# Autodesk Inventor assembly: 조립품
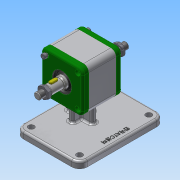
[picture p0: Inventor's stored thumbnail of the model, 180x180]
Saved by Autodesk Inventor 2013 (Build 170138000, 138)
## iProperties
Created: 2020-11
Part Number: 조립품
Document SubType Name: Assembly
Designer: Administrator
Author: Administrator
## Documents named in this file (10)
- C:\Users\Administrator\Desktop\701106V1009\조립품.iam
- C:\Users\Administrator\Desktop\701106V1009\본체.ipt
- C:\Users\Administrator\Desktop\701106V1009\V-벨트풀리.ipt
- C:\Users\Administrator\Desktop\701106V1009\너트 M10x1.ipt
- C:\Users\Administrator\Desktop\701106V1009\베어링 6004.ipt
- C:\Users\Administrator\Desktop\701106V1009\볼트 M4.ipt
- C:\Users\Administrator\Desktop\701106V1009\오일 실 17 30 5.ipt
- C:\Users\Administrator\Desktop\701106V1009\축.ipt
- C:\Users\Administrator\Desktop\701106V1009\커버.ipt
- C:\Users\Administrator\Desktop\701106V1009\키 5 x 5 x 12.ipt
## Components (2 placed, 1 different names)
1. V-벨트풀리:1
2. V-벨트풀리:2
